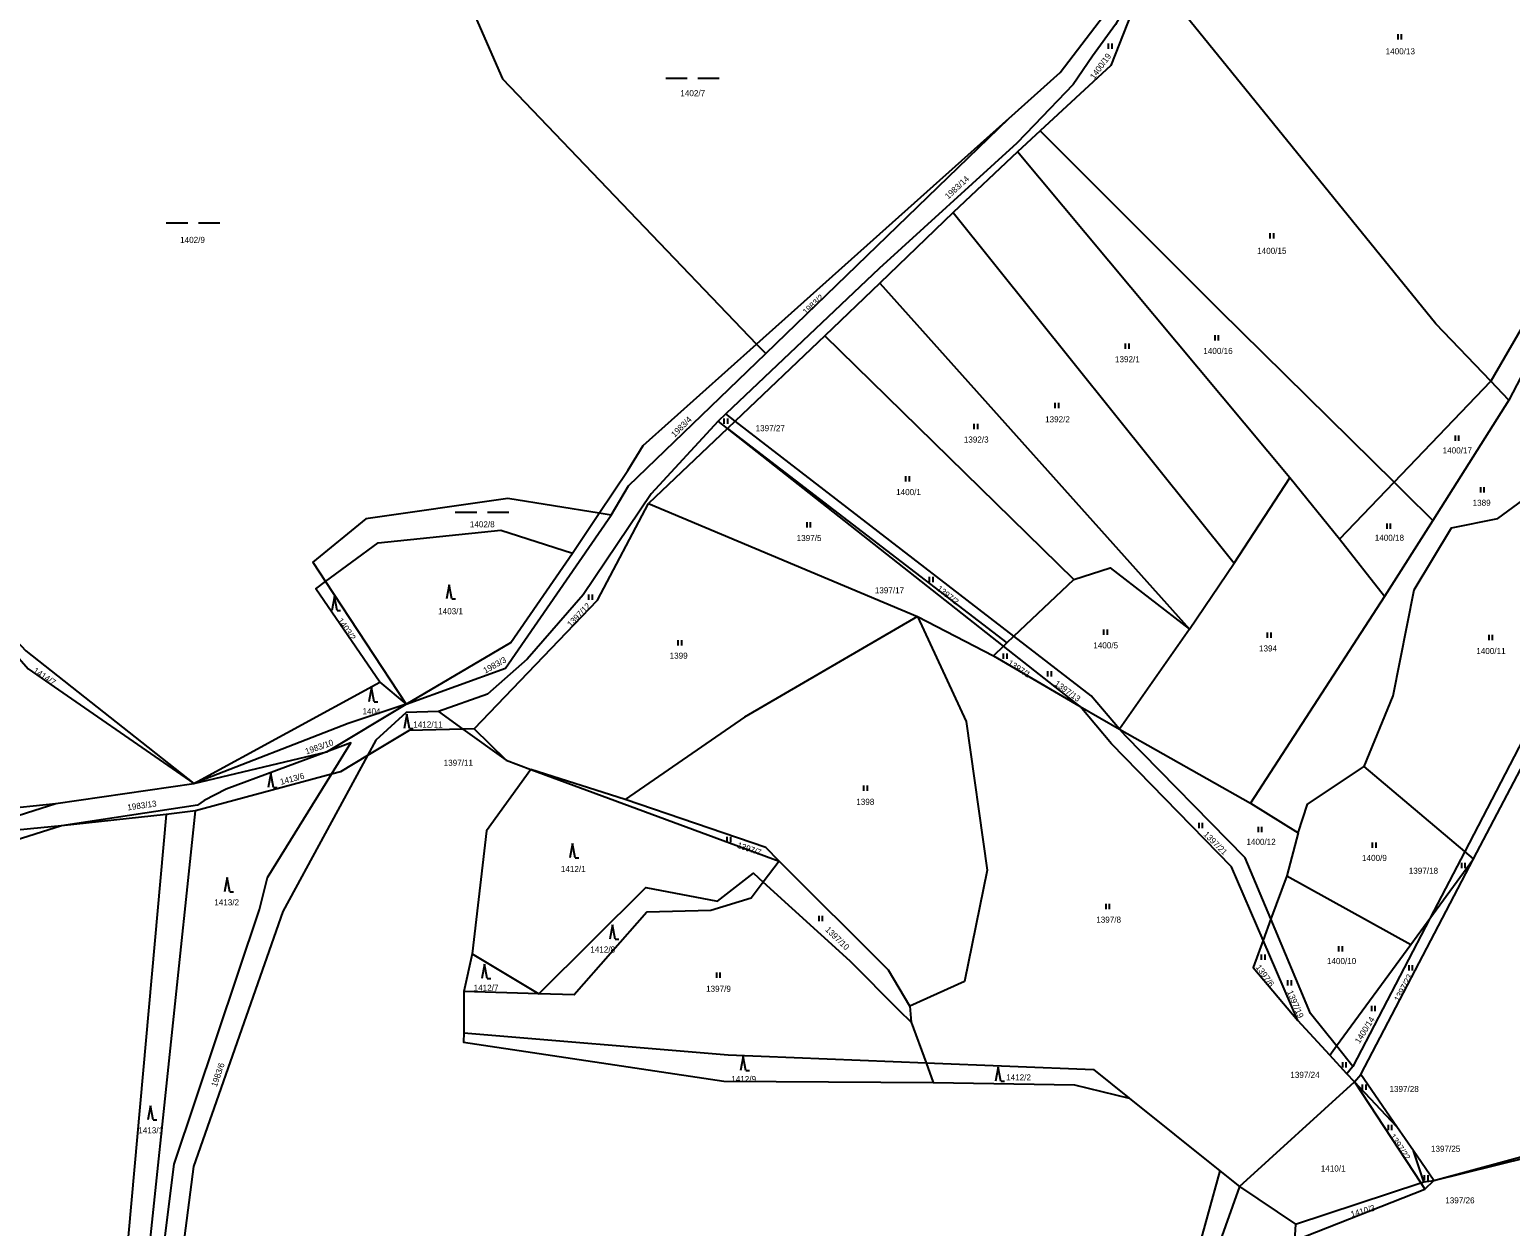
# Model space of a CAD drawing. Extents: x -793666 to -785424, y -1118958 to -1108761.
# Drawn here: x -786143.7 to -785728.5, y -1118559.9 to -1118224.3 of the extents above; entities that cross this region are included whole.
import ezdxf

# ---------------------------------------------------------------- set-up
doc = ezdxf.new("R2010")
doc.units = 0
for name, color, linetype in [('Hranice parcel', 7, 'Continuous'), ('Parcelní čísla', 7, 'Continuous'), ('Značky kultur', 7, 'Continuous')]:
    doc.layers.add(name, color=color, linetype=linetype)

msp = doc.modelspace()

# ---------------------------------------------------------------- linework, layer by layer
at = {"layer": 'Hranice parcel'}
for p, q in [((-785869.09, -1118249.17), (-785939.83, -1118312.47)), ((-785937.27, -1118315.15), (-785869.09, -1118249.17)), ((-785690.96, -1118248.39), (-785733.96, -1118322.91)), ((-785860.34, -1118252.67), (-785866.68, -1118258.52)), ((-785866.68, -1118258.52), (-785884.67, -1118275.53)), ((-785790.34, -1118349.99), (-785866.68, -1118258.52)), ((-785884.67, -1118275.53), (-785905.32, -1118295.4)), ((-785884.67, -1118275.53), (-785805.93, -1118373.88)), ((-785905.32, -1118295.4), (-785920.69, -1118310.17)), ((-785905.32, -1118295.4), (-785818.48, -1118392.46)), ((-785713.36, -1118298.16), (-785728.89, -1118328.21)), ((-785920.69, -1118310.17), (-785945.81, -1118334.05)), ((-785850.86, -1118378.51), (-785920.69, -1118310.17)), ((-785939.83, -1118312.47), (-785937.27, -1118315.15)), ((-785761.07, -1118351.19), (-785733.96, -1118322.91)), ((-785728.89, -1118328.21), (-785733.96, -1118322.91)), ((-785728.89, -1118328.21), (-785750.24, -1118361.91)), ((-785948.43, -1118332.03), (-785950.6, -1118334.1)), ((-785945.81, -1118334.05), (-785948.43, -1118332.03)), ((-785948.01, -1118336.14), (-785970.16, -1118357.21)), ((-785948.01, -1118336.14), (-785950.6, -1118334.1)), ((-785945.81, -1118334.05), (-785948.01, -1118336.14)), ((-785948.01, -1118336.14), (-785869.63, -1118396.21)), ((-785870.61, -1118397.17), (-785948.01, -1118336.14)), ((-785867.68, -1118394.37), (-785945.81, -1118334.05)), ((-785805.93, -1118373.88), (-785790.34, -1118349.99)), ((-785776.41, -1118367.19), (-785790.34, -1118349.99)), ((-785776.41, -1118367.19), (-785761.07, -1118351.19)), ((-785970.16, -1118357.21), (-785894.73, -1118388.89)), ((-785991.45, -1118371.11), (-785983.95, -1118359.9)), ((-785980.65, -1118360.44), (-785983.95, -1118359.9)), ((-785750.24, -1118361.91), (-785763.75, -1118383.23)), ((-785763.75, -1118383.23), (-785776.41, -1118367.19)), ((-785738.78, -1118456.85), (-785691.24, -1118365.94)), ((-785818.48, -1118392.46), (-785805.93, -1118373.88)), ((-786060.66, -1118379.07), (-786038.12, -1118413.46)), ((-785867.68, -1118394.37), (-785850.86, -1118378.51)), ((-785763.75, -1118383.23), (-785801.35, -1118441.22)), ((-785894.73, -1118388.89), (-785873.39, -1118399.87)), ((-785869.63, -1118396.21), (-785867.68, -1118394.37)), ((-785818.48, -1118392.46), (-785838.04, -1118420.43)), ((-785870.61, -1118397.17), (-785873.39, -1118399.87)), ((-785869.63, -1118396.21), (-785870.61, -1118397.17)), ((-785849.12, -1118414.11), (-785870.61, -1118397.17)), ((-785873.39, -1118399.87), (-785849.12, -1118414.11)), ((-786097.63, -1118435.75), (-786045.47, -1118407.25)), ((-786045.47, -1118407.25), (-786038.12, -1118413.46)), ((-786060.37, -1118426.83), (-786038.12, -1118413.46)), ((-786029, -1118415.53), (-786022.21, -1118420.42)), ((-785849.12, -1118414.11), (-785838.04, -1118420.43)), ((-786018.99, -1118420.34), (-786022.21, -1118420.42)), ((-786022.21, -1118420.42), (-786010.02, -1118429.2)), ((-786010.02, -1118429.2), (-786018.99, -1118420.34)), ((-785838.04, -1118420.43), (-785801.35, -1118441.22)), ((-786097.63, -1118435.75), (-786060.37, -1118426.83)), ((-786010.02, -1118429.2), (-786003.1, -1118431.76)), ((-785976.67, -1118440.16), (-786003.1, -1118431.76)), ((-786003.1, -1118431.76), (-785933.46, -1118457.47)), ((-785741.28, -1118454.74), (-785769.49, -1118430.92)), ((-786136.35, -1118441.28), (-786097.63, -1118435.75)), ((-786059.03, -1118433.1), (-786097.17, -1118443.33)), ((-786165.45, -1118450.61), (-786136.35, -1118441.28)), ((-786105.36, -1118444.39), (-786134.76, -1118447.56)), ((-786114.45, -1118608.23), (-786097.17, -1118443.33)), ((-786097.17, -1118443.33), (-786105.36, -1118444.39)), ((-785801.35, -1118441.22), (-785787.94, -1118449.58)), ((-786134.76, -1118447.56), (-786165.45, -1118450.61)), ((-785787.94, -1118449.58), (-785791.2, -1118461.6)), ((-785770.4, -1118517.32), (-785738.78, -1118456.85)), ((-785741.28, -1118454.74), (-785751.09, -1118473.61)), ((-785751.09, -1118473.61), (-785738.78, -1118456.85)), ((-785738.78, -1118456.85), (-785741.28, -1118454.74)), ((-785933.46, -1118457.47), (-785937.95, -1118463.36)), ((-785791.2, -1118461.6), (-785795.63, -1118473.66)), ((-785791.2, -1118461.6), (-785756.39, -1118480.83)), ((-785795.63, -1118473.66), (-785797.83, -1118479.65)), ((-785751.09, -1118473.61), (-785772.64, -1118515.08)), ((-785756.39, -1118480.83), (-785751.09, -1118473.61)), ((-785788.09, -1118502.2), (-785797.83, -1118479.65)), ((-785777.24, -1118509.29), (-785756.39, -1118480.83)), ((-786019.59, -1118483.5), (-786021.94, -1118494.06)), ((-786019.59, -1118483.5), (-786000.93, -1118494.68)), ((-786000.93, -1118494.68), (-786021.94, -1118494.06)), ((-786021.94, -1118494.06), (-786021.93, -1118505.63)), ((-785896.84, -1118498.13), (-785896.45, -1118502.65)), ((-785896.45, -1118502.65), (-785892.33, -1118514.03)), ((-785779.14, -1118511.87), (-785788.09, -1118502.2)), ((-785779.14, -1118511.87), (-785777.24, -1118509.29)), ((-785772.64, -1118515.08), (-785777.24, -1118509.29)), ((-785892.33, -1118514.03), (-785890.33, -1118519.57)), ((-785774.3, -1118517.1), (-785779.14, -1118511.87)), ((-785772.64, -1118515.08), (-785774.3, -1118517.1)), ((-785804.39, -1118548.75), (-785772.21, -1118519.36)), ((-785772.21, -1118519.36), (-785774.3, -1118517.1)), ((-785772.21, -1118519.36), (-785770.4, -1118517.32)), ((-785760.29, -1118531.99), (-785772.21, -1118519.36)), ((-785772.21, -1118519.36), (-785753.62, -1118547.72)), ((-785760.29, -1118531.99), (-785770.4, -1118517.32)), ((-785835.35, -1118523.95), (-785809.94, -1118544.3)), ((-785749.91, -1118547.06), (-785665.83, -1118524.09)), ((-785755.66, -1118538.71), (-785760.29, -1118531.99)), ((-785752.74, -1118547.43), (-785755.66, -1118538.71)), ((-785749.91, -1118547.06), (-785755.66, -1118538.71)), ((-785809.94, -1118544.3), (-785826.56, -1118604.28)), ((-785809.94, -1118544.3), (-785804.39, -1118548.75)), ((-785788.74, -1118559.33), (-785753.62, -1118547.72)), ((-785753.62, -1118547.72), (-785752.74, -1118547.43)), ((-785753.62, -1118547.72), (-785752.48, -1118549.46)), ((-785752.74, -1118547.43), (-785749.91, -1118547.06)), ((-785752.48, -1118549.46), (-785749.91, -1118547.06)), ((-785804.39, -1118548.75), (-785788.74, -1118559.33)), ((-785788.98, -1118563.83), (-785752.48, -1118549.46)), ((-785788.74, -1118559.33), (-785788.98, -1118563.83))]:
    msp.add_line(p, q, dxfattribs=at)
for points in [[(-785790.45, -1118102.52), (-785825.31, -1118187.93), (-785834.75, -1118214.64), (-785839.18, -1118222.8), (-785845.61, -1118231.69), (-785851.07, -1118239.66), (-785862.03, -1118251.08), (-785866.85, -1118256.11), (-785905.45, -1118291.29), (-785948.43, -1118332.03)], [(-786107.31, -1118105.75), (-786056.01, -1118135.27), (-786011.03, -1118238.08), (-785939.83, -1118312.47)], [(-785829.99, -1118207.38), (-785840.54, -1118234.38), (-785860.34, -1118252.67)], [(-785733.96, -1118322.91), (-785749.37, -1118306.81), (-785829.99, -1118207.38)], [(-785869.09, -1118249.17), (-785854.74, -1118236.32), (-785842.59, -1118220.42), (-785842.75, -1118218.11)], [(-785860.34, -1118252.67), (-785810.14, -1118302.82), (-785761.07, -1118351.19)], [(-785983.95, -1118359.9), (-785975.9, -1118347.89), (-785971.6, -1118340.9), (-785939.83, -1118312.47)], [(-785980.65, -1118360.44), (-785975.79, -1118352.21), (-785937.27, -1118315.15)], [(-785950.6, -1118334.1), (-785969.39, -1118354.51), (-785988.42, -1118382.79), (-786004.15, -1118400.86), (-786015.25, -1118410.62), (-786029, -1118415.53)], [(-786200.27, -1118339.1), (-786144.03, -1118403.55), (-786097.63, -1118435.75)], [(-786200.27, -1118339.1), (-786144.71, -1118398.48), (-786097.63, -1118435.75)], [(-785761.07, -1118351.19), (-785758.14, -1118354.07), (-785750.24, -1118361.91)], [(-785983.95, -1118359.9), (-786009.6, -1118355.74), (-786049.37, -1118361.49), (-786064.25, -1118373.59), (-786060.66, -1118379.07)], [(-786018.99, -1118420.34), (-785984.39, -1118384.26), (-785970.16, -1118357.21)], [(-785769.49, -1118430.92), (-785761.38, -1118411.16), (-785755.43, -1118381.43), (-785744.97, -1118364.02), (-785731.99, -1118361.41), (-785723.55, -1118355.19)], [(-786038.12, -1118413.46), (-786010.19, -1118403.36), (-785980.65, -1118360.44)], [(-786060.66, -1118379.07), (-786045.92, -1118368.23), (-786011.57, -1118364.62), (-785991.45, -1118371.11)], [(-785695.38, -1118364.56), (-785695.93, -1118367.45), (-785741.28, -1118454.74)], [(-786038.12, -1118413.46), (-786008.7, -1118396.12), (-785991.45, -1118371.11)], [(-785850.86, -1118378.51), (-785840.71, -1118375.26), (-785818.48, -1118392.46)], [(-786045.47, -1118407.25), (-786063.45, -1118381.12), (-786060.66, -1118379.07)], [(-785894.73, -1118388.89), (-785943.25, -1118417.14), (-785976.67, -1118440.16)], [(-785894.73, -1118388.89), (-785881.08, -1118418.32), (-785875.22, -1118460.03), (-785881.57, -1118491.19), (-785896.84, -1118498.13)], [(-785838.04, -1118420.43), (-785845.99, -1118411.11), (-785867.68, -1118394.37)], [(-786038.12, -1118413.46), (-786054.35, -1118418.84), (-786097.63, -1118435.75)], [(-786029, -1118415.53), (-786038.05, -1118415.81), (-786046.56, -1118423.54), (-786048.89, -1118427.82)], [(-785797.83, -1118479.65), (-785806.7, -1118459.1), (-785840.31, -1118424.57), (-785849.12, -1118414.11)], [(-786022.21, -1118420.42), (-786037.27, -1118420.81), (-786048.89, -1118427.82)], [(-785795.63, -1118473.66), (-785802.81, -1118456.59), (-785836.38, -1118422.38), (-785838.04, -1118420.43)], [(-786060.37, -1118426.83), (-786088.59, -1118437.3), (-786094.72, -1118440.44), (-786096.6, -1118441.76), (-786134.76, -1118447.56)], [(-786048.89, -1118427.82), (-786072.67, -1118471.58), (-786097.69, -1118543.13), (-786104.44, -1118595.02), (-786120.51, -1118642.74)], [(-786059.03, -1118433.1), (-786053.6, -1118424.32), (-786060.37, -1118426.83)], [(-786048.89, -1118427.82), (-786056.51, -1118432.42), (-786059.03, -1118433.1)], [(-786003.1, -1118431.76), (-786015.52, -1118448.98), (-786019.59, -1118483.5)], [(-785787.94, -1118449.58), (-785785.41, -1118441.49), (-785769.49, -1118430.92)], [(-786114.45, -1118608.23), (-786109.6, -1118593.93), (-786103.17, -1118542.43), (-786079.19, -1118471.01), (-786076.97, -1118462.09), (-786059.03, -1118433.1)], [(-785933.46, -1118457.47), (-785937.2, -1118453.65), (-785976.67, -1118440.16)], [(-786328.74, -1118490.83), (-786234.58, -1118451.39), (-786136.35, -1118441.28)], [(-786105.36, -1118444.39), (-786119.23, -1118598.18), (-786127.09, -1118645.52)], [(-786134.76, -1118447.56), (-786269.81, -1118490.34), (-786310.04, -1118492.63), (-786320.06, -1118493.54)], [(-786000.93, -1118494.68), (-785970.93, -1118464.85), (-785950.8, -1118468.72), (-785940.68, -1118460.88), (-785937.95, -1118463.36)], [(-785896.84, -1118498.13), (-785902.89, -1118488.01), (-785933.46, -1118457.47)], [(-785937.95, -1118463.36), (-785941.38, -1118467.86), (-785952.67, -1118471.36), (-785970.56, -1118471.8), (-785991, -1118494.97), (-786000.93, -1118494.68)], [(-785896.45, -1118502.65), (-785899.8, -1118499.48), (-785913.61, -1118485.49), (-785937.95, -1118463.36)], [(-785777.24, -1118509.29), (-785784.48, -1118500.17), (-785795.63, -1118473.66)], [(-785797.83, -1118479.65), (-785800.63, -1118487.27), (-785788.09, -1118502.2)], [(-786021.93, -1118505.63), (-786021.99, -1118508.26), (-785949, -1118519.17), (-785890.33, -1118519.57)], [(-786021.93, -1118505.63), (-785947.82, -1118511.83), (-785892.33, -1118514.03)], [(-785892.33, -1118514.03), (-785845.41, -1118515.89), (-785835.35, -1118523.95)], [(-785890.33, -1118519.57), (-785850.72, -1118520.25), (-785835.35, -1118523.95)], [(-785749.91, -1118547.06), (-785671.01, -1118527.5), (-785651.03, -1118530.87)], [(-785804.39, -1118548.75), (-785823.15, -1118601.29), (-785826.56, -1118604.28)]]:
    msp.add_lwpolyline(points, dxfattribs=at)
at = {"layer": 'Značky kultur'}
for p, q in [((-785841.16, -1118229.69), (-785841.16, -1118228.19)), ((-785840.16, -1118229.69), (-785840.16, -1118228.19)), ((-785759.98, -1118227.07), (-785759.98, -1118225.57)), ((-785758.98, -1118227.07), (-785758.98, -1118225.57)), ((-785965.31, -1118237.9), (-785959.31, -1118237.9)), ((-785956.31, -1118237.9), (-785950.31, -1118237.9)), ((-786105.33, -1118278.46), (-786099.33, -1118278.46)), ((-786096.33, -1118278.46), (-786090.33, -1118278.46)), ((-785795.82, -1118282.87), (-785795.82, -1118281.37)), ((-785794.82, -1118282.87), (-785794.82, -1118281.37)), ((-785811.3, -1118311.42), (-785811.3, -1118309.92)), ((-785810.3, -1118311.42), (-785810.3, -1118309.92)), ((-785836.37, -1118313.77), (-785836.37, -1118312.27)), ((-785835.37, -1118313.77), (-785835.37, -1118312.27)), ((-785856.07, -1118330.48), (-785856.07, -1118328.98)), ((-785855.07, -1118330.48), (-785855.07, -1118328.98)), ((-785948.93, -1118334.87), (-785948.93, -1118333.37)), ((-785947.93, -1118334.87), (-785947.93, -1118333.37)), ((-785878.78, -1118336.31), (-785878.78, -1118334.81)), ((-785877.78, -1118336.31), (-785877.78, -1118334.81)), ((-785743.89, -1118339.64), (-785743.89, -1118338.14)), ((-785742.89, -1118339.64), (-785742.89, -1118338.14)), ((-785897.94, -1118350.97), (-785897.94, -1118349.47)), ((-785896.94, -1118350.97), (-785896.94, -1118349.47)), ((-785736.81, -1118354.1), (-785736.81, -1118352.6)), ((-785735.81, -1118354.1), (-785735.81, -1118352.6)), ((-786024.31, -1118359.58), (-786018.31, -1118359.58)), ((-786015.31, -1118359.58), (-786009.31, -1118359.58)), ((-785925.69, -1118363.87), (-785925.69, -1118362.37)), ((-785924.69, -1118363.87), (-785924.69, -1118362.37)), ((-785763.06, -1118364.26), (-785763.06, -1118362.76)), ((-785762.06, -1118364.26), (-785762.06, -1118362.76)), ((-785891.32, -1118379.21), (-785891.32, -1118377.71)), ((-785890.32, -1118379.21), (-785890.32, -1118377.71)), ((-786026, -1118379.94), (-786026.75, -1118383.94)), ((-786025.25, -1118383.94), (-786026, -1118379.94)), ((-786058.22, -1118383.23), (-786058.97, -1118387.23)), ((-786057.47, -1118387.23), (-786058.22, -1118383.23)), ((-786025.25, -1118383.94), (-786024.25, -1118383.94)), ((-785986.85, -1118384.19), (-785986.85, -1118382.69)), ((-785985.85, -1118384.19), (-785985.85, -1118382.69)), ((-786057.47, -1118387.23), (-786056.47, -1118387.23)), ((-785842.46, -1118394.02), (-785842.46, -1118392.52)), ((-785841.46, -1118394.02), (-785841.46, -1118392.52)), ((-785796.56, -1118394.81), (-785796.56, -1118393.31)), ((-785795.56, -1118394.81), (-785795.56, -1118393.31)), ((-785734.45, -1118395.55), (-785734.45, -1118394.05)), ((-785733.45, -1118395.55), (-785733.45, -1118394.05)), ((-785961.82, -1118396.96), (-785961.82, -1118395.46)), ((-785960.82, -1118396.96), (-785960.82, -1118395.46)), ((-785870.59, -1118400.75), (-785870.59, -1118399.25)), ((-785869.59, -1118400.75), (-785869.59, -1118399.25)), ((-785858.15, -1118405.7), (-785858.15, -1118404.2)), ((-785857.15, -1118405.7), (-785857.15, -1118404.2)), ((-786047.78, -1118408.8), (-786048.53, -1118412.8)), ((-786047.03, -1118412.8), (-786047.78, -1118408.8)), ((-786047.03, -1118412.8), (-786046.03, -1118412.8)), ((-786037.91, -1118416.28), (-786038.66, -1118420.28)), ((-786037.16, -1118420.28), (-786037.91, -1118416.28)), ((-786037.16, -1118420.28), (-786036.16, -1118420.28)), ((-786076.04, -1118432.85), (-786076.79, -1118436.85)), ((-786075.29, -1118436.85), (-786076.04, -1118432.85)), ((-785909.73, -1118437.76), (-785909.73, -1118436.26)), ((-785908.73, -1118437.76), (-785908.73, -1118436.26)), ((-786075.29, -1118436.85), (-786074.29, -1118436.85)), ((-785815.78, -1118448.22), (-785815.78, -1118446.72)), ((-785814.78, -1118448.22), (-785814.78, -1118446.72)), ((-785799.15, -1118449.32), (-785799.15, -1118447.82)), ((-785798.15, -1118449.32), (-785798.15, -1118447.82)), ((-785991.45, -1118452.57), (-785992.2, -1118456.57)), ((-785990.7, -1118456.57), (-785991.45, -1118452.57)), ((-785948.05, -1118452.15), (-785948.05, -1118450.65)), ((-785947.05, -1118452.15), (-785947.05, -1118450.65)), ((-785767.1, -1118453.75), (-785767.1, -1118452.25)), ((-785766.1, -1118453.75), (-785766.1, -1118452.25)), ((-785990.7, -1118456.57), (-785989.7, -1118456.57)), ((-785742.13, -1118459.41), (-785742.13, -1118457.91)), ((-785741.13, -1118459.41), (-785741.13, -1118457.91)), ((-786088.27, -1118462.06), (-786089.02, -1118466.06)), ((-786087.52, -1118466.06), (-786088.27, -1118462.06)), ((-786087.52, -1118466.06), (-786086.52, -1118466.06)), ((-785841.85, -1118470.94), (-785841.85, -1118469.44)), ((-785840.85, -1118470.94), (-785840.85, -1118469.44)), ((-785922.31, -1118474.35), (-785922.31, -1118472.85)), ((-785921.31, -1118474.35), (-785921.31, -1118472.85)), ((-785980.22, -1118475.35), (-785980.97, -1118479.35)), ((-785979.47, -1118479.35), (-785980.22, -1118475.35)), ((-785979.47, -1118479.35), (-785978.47, -1118479.35)), ((-785776.58, -1118482.82), (-785776.58, -1118481.32)), ((-785775.58, -1118482.82), (-785775.58, -1118481.32)), ((-785798.24, -1118485.15), (-785798.24, -1118483.65)), ((-785797.24, -1118485.15), (-785797.24, -1118483.65)), ((-786016.11, -1118486.35), (-786016.86, -1118490.35)), ((-786015.36, -1118490.35), (-786016.11, -1118486.35)), ((-786015.36, -1118490.35), (-786014.36, -1118490.35)), ((-785951.02, -1118490.17), (-785951.02, -1118488.67)), ((-785950.02, -1118490.17), (-785950.02, -1118488.67)), ((-785756.89, -1118488.13), (-785756.89, -1118486.63)), ((-785755.89, -1118488.13), (-785755.89, -1118486.63)), ((-785790.84, -1118492.32), (-785790.84, -1118490.82)), ((-785789.84, -1118492.32), (-785789.84, -1118490.82)), ((-785767.35, -1118499.55), (-785767.35, -1118498.05)), ((-785766.35, -1118499.55), (-785766.35, -1118498.05)), ((-785943.55, -1118512.23), (-785944.3, -1118516.23)), ((-785942.8, -1118516.23), (-785943.55, -1118512.23)), ((-785872.09, -1118515.23), (-785872.84, -1118519.23)), ((-785871.34, -1118519.23), (-785872.09, -1118515.23)), ((-785775.48, -1118515.33), (-785775.48, -1118513.83)), ((-785774.48, -1118515.33), (-785774.48, -1118513.83)), ((-785942.8, -1118516.23), (-785941.8, -1118516.23)), ((-785871.34, -1118519.23), (-785870.34, -1118519.23)), ((-785769.91, -1118521.59), (-785769.91, -1118520.09)), ((-785768.91, -1118521.59), (-785768.91, -1118520.09)), ((-786109.76, -1118526.06), (-786110.51, -1118530.06)), ((-786109.01, -1118530.06), (-786109.76, -1118526.06)), ((-786109.01, -1118530.06), (-786108.01, -1118530.06)), ((-785762.7, -1118532.97), (-785762.7, -1118531.47)), ((-785761.7, -1118532.97), (-785761.7, -1118531.47)), ((-785752.55, -1118547.03), (-785752.55, -1118545.53)), ((-785751.55, -1118547.03), (-785751.55, -1118545.53))]:
    msp.add_line(p, q, dxfattribs=at)

# ---------------------------------------------------------------- texts
at = {"layer": 'Parcelní čísla'}
for s, rotation, p in [('1400/19', 54, (-785845.12, -1118238.35)), ('1983/14', 43, (-785886.08, -1118271.94)), ('1983/2', 43, (-785925.93, -1118304.34)), ('1983/4', 45, (-785962.78, -1118338.71)), ('1397/2', 322, (-785889.46, -1118381.39)), ('1397/12', 46, (-785991.92, -1118391.95)), ('1403/2', 305, (-786057.44, -1118390.04)), ('1983/3', 29, (-786015.88, -1118404.91)), ('1397/1', 327, (-785869.58, -1118402.32)), ('1414/7', 327, (-786142.84, -1118404.48)), ('1397/13', 324, (-785856.46, -1118408.06)), ('1983/10', 19, (-786066.06, -1118427.57)), ('1413/6', 15, (-786073.18, -1118436.1)), ('1983/13', 8, (-786116.13, -1118443.27)), ('1397/7', 341, (-785945.45, -1118453.68)), ('1397/21', 315, (-785814.66, -1118450.14)), ('1397/10', 316, (-785920.72, -1118476.88)), ('1397/6', 306, (-785799.98, -1118487.28)), ('1397/23', 62, (-785759.67, -1118497.03)), ('1397/19', 293, (-785791.13, -1118494.13)), ('1400/14', 58, (-785770.78, -1118508.78)), ('1983/6', 71, (-786091.2, -1118520.94)), ('1397/22', 304, (-785762.41, -1118534.7)), ('1410/3', 16, (-785772.99, -1118557.37))]:
    msp.add_text(s, height=1.7, rotation=rotation, dxfattribs=at).set_placement(p)
for s, p in [('1400/13', (-785763.45, -1118231.2)), ('1402/7', (-785961.2, -1118242.94)), ('1402/9', (-786101.46, -1118284.09)), ('1400/15', (-785799.48, -1118287.16)), ('1392/1', (-785839.34, -1118317.56)), ('1400/16', (-785814.57, -1118315.23)), ('1392/2', (-785858.94, -1118334.41)), ('1397/27', (-785940.11, -1118336.9)), ('1392/3', (-785881.73, -1118340.09)), ('1400/17', (-785747.47, -1118343.14)), ('1400/1', (-785900.71, -1118354.83)), ('1389', (-785739.07, -1118357.82)), ('1402/8', (-786020.22, -1118363.86)), ('1400/18', (-785766.51, -1118367.64)), ('1397/5', (-785928.59, -1118367.71)), ('1397/17', (-785906.68, -1118382.37)), ('1403/1', (-786029.11, -1118388.23)), ('1399', (-785964.21, -1118400.7)), ('1400/5', (-785845.42, -1118397.81)), ('1394', (-785798.96, -1118398.67)), ('1400/11', (-785738.04, -1118399.4)), ('1404', (-786050.33, -1118416.28)), ('1412/11', (-786036.09, -1118420.01)), ('1397/11', (-786027.57, -1118430.74)), ('1398', (-785911.87, -1118441.69)), ('1400/12', (-785802.49, -1118452.91)), ('1400/9', (-785770.07, -1118457.42)), ('1412/1', (-785994.71, -1118460.53)), ('1397/18', (-785756.97, -1118461.03)), ('1413/2', (-786091.89, -1118469.89)), ('1397/8', (-785844.6, -1118474.74)), ('1412/8', (-785986.45, -1118483.11)), ('1400/10', (-785779.92, -1118486.35)), ('1412/7', (-786019.15, -1118493.84)), ('1397/9', (-785953.99, -1118494.12)), ('1412/9', (-785946.93, -1118519.43)), ('1412/2', (-785869.86, -1118518.99)), ('1397/24', (-785790.17, -1118518.26)), ('1397/28', (-785762.38, -1118522.22)), ('1413/1', (-786113.19, -1118533.82)), ('1397/25', (-785750.74, -1118538.99)), ('1410/1', (-785781.64, -1118544.53)), ('1397/26', (-785746.74, -1118553.46))]:
    msp.add_text(s, height=1.7, dxfattribs=at).set_placement(p)

doc.saveas('drawing.dxf')
